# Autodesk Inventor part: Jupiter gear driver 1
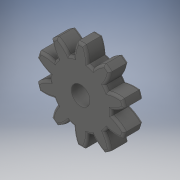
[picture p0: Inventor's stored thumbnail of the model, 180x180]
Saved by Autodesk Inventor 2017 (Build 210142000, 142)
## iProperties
Created: 2016-05
Part Number: Jupiter gear driver 1
Material: Generic
Document SubType Name: Modeling
Designer: Stan
Density: 1 g/cm^3
Appearance: Gray
Author: Stan
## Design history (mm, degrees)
sketch "Sketch1"
  geometry: A1 r 11.357 centre (-12.259, -5.358) between (-9.02, 5.527) and (-14.115, 5.847); A2 r 11.357 centre (-12.259, -5.358) between (-9.02, 5.527) and (-14.115, 5.847); A3 r 11.357 centre (1.307, 13.315) between (-9.922, 11.617) and (-8.044, 6.87); A4 r 11.357 centre (1.307, 13.315) between (-9.922, 11.617) and (-8.044, 6.87); A5 r 11.357 centre (-6.769, -11.54) between (-10.546, -0.83) and (-14.856, -3.567); A6 r 11.357 centre (-6.769, -11.54) between (-10.546, -0.83) and (-14.856, -3.567); A7 r 11.357 centre (-6.769, 11.54) between (-14.856, 3.567) and (-10.546, 0.83); A8 r 11.357 centre (-6.769, 11.54) between (-14.856, 3.567) and (-10.546, 0.83); A9 r 11.357 centre (1.307, -13.315) between (-8.044, -6.87) and (-9.922, -11.617); A10 r 11.357 centre (1.307, -13.315) between (-8.044, -6.87) and (-9.922, -11.617); A11 r 11.357 centre (-12.259, 5.358) between (-14.115, -5.847) and (-9.02, -5.527); A12 r 11.357 centre (-12.259, 5.358) between (-14.115, -5.847) and (-9.02, -5.527); A13 r 11.357 centre (8.884, -10.004) between (-2.47, -10.287) and (-1.199, -15.231); A14 r 11.357 centre (8.884, -10.004) between (-2.47, -10.287) and (-1.199, -15.231); A15 r 11.357 centre (-13.067, -2.871) between (-7.983, -13.027) and (-4.048, -9.774); A16 r 11.357 centre (-13.067, -2.871) between (-7.983, -13.027) and (-4.048, -9.774); A17 r 11.357 centre (13.067, -2.871) between (4.048, -9.774) and (7.983, -13.027); A18 r 11.357 centre (13.067, -2.871) between (4.048, -9.774) and (7.983, -13.027); A19 r 11.357 centre (-8.884, -10.004) between (1.199, -15.231) and (2.47, -10.287); A20 r 11.357 centre (-8.884, -10.004) between (1.199, -15.231) and (2.47, -10.287); A21 r 11.357 centre (12.259, 5.358) between (9.02, -5.527) and (14.115, -5.847); A22 r 11.357 centre (12.259, 5.358) between (9.02, -5.527) and (14.115, -5.847); A23 r 11.357 centre (-1.307, -13.315) between (9.922, -11.617) and (8.044, -6.87); A24 r 11.357 centre (-1.307, -13.315) between (9.922, -11.617) and (8.044, -6.87); A25 r 11.357 centre (6.769, 11.54) between (10.546, 0.83) and (14.856, 3.567); A26 r 11.357 centre (6.769, 11.54) between (10.546, 0.83) and (14.856, 3.567); A27 r 11.357 centre (6.769, -11.54) between (14.856, -3.567) and (10.546, -0.83); A28 r 11.357 centre (6.769, -11.54) between (14.856, -3.567) and (10.546, -0.83); A29 r 11.357 centre (-1.307, 13.315) between (8.044, 6.87) and (9.922, 11.617); A30 r 11.357 centre (-1.307, 13.315) between (8.044, 6.87) and (9.922, 11.617); A31 r 11.357 centre (12.259, -5.358) between (14.115, 5.847) and (9.02, 5.527); A32 r 11.357 centre (12.259, -5.358) between (14.115, 5.847) and (9.02, 5.527); A33 r 11.357 centre (-8.884, 10.004) between (2.47, 10.287) and (1.199, 15.231); A34 r 11.357 centre (-8.884, 10.004) between (2.47, 10.287) and (1.199, 15.231); A35 r 11.357 centre (13.067, 2.871) between (7.983, 13.027) and (4.048, 9.774); A36 r 11.357 centre (13.067, 2.871) between (7.983, 13.027) and (4.048, 9.774); A37 r 11.357 centre (1.307, 13.315) between (-9.922, 11.617) and (-8.044, 6.87); A38 r 11.357 centre (-12.259, -5.358) between (-9.02, 5.527) and (-14.115, 5.847); A39 r 11.357 centre (-6.769, 11.54) between (-14.856, 3.567) and (-10.546, 0.83); A40 r 11.357 centre (-6.769, -11.54) between (-10.546, -0.83) and (-14.856, -3.567); A41 r 11.357 centre (-12.259, 5.358) between (-14.115, -5.847) and (-9.02, -5.527); A42 r 11.357 centre (1.307, -13.315) between (-8.044, -6.87) and (-9.922, -11.617); A43 r 11.357 centre (-13.067, -2.871) between (-7.983, -13.027) and (-4.048, -9.774); A44 r 11.357 centre (8.884, -10.004) between (-2.47, -10.287) and (-1.199, -15.231); A45 r 11.357 centre (-8.884, -10.004) between (1.199, -15.231) and (2.47, -10.287); A46 r 11.357 centre (13.067, -2.871) between (4.048, -9.774) and (7.983, -13.027); A47 r 11.357 centre (-1.307, -13.315) between (9.922, -11.617) and (8.044, -6.87); A48 r 11.357 centre (12.259, 5.358) between (9.02, -5.527) and (14.115, -5.847); A49 r 11.357 centre (6.769, -11.54) between (14.856, -3.567) and (10.546, -0.83); A50 r 11.357 centre (6.769, 11.54) between (10.546, 0.83) and (14.856, 3.567); A51 r 11.357 centre (12.259, -5.358) between (14.115, 5.847) and (9.02, 5.527); A52 r 11.357 centre (-1.307, 13.315) between (8.044, 6.87) and (9.922, 11.617); A53 r 11.357 centre (13.067, 2.871) between (7.983, 13.027) and (4.048, 9.774); A54 r 11.357 centre (-8.884, 10.004) between (2.47, 10.287) and (1.199, 15.231); A55 r 11.357 centre (8.884, 10.004) between (-1.199, 15.231) and (-2.47, 10.287); A56 r 11.357 centre (-13.067, 2.871) between (-4.048, 9.774) and (-7.983, 13.027); A57 r 11.357 centre (-13.067, 2.871) between (-4.048, 9.774) and (-7.983, 13.027); A58 r 11.357 centre (-13.067, 2.871) between (-4.048, 9.774) and (-7.983, 13.027); A59 r 11.357 centre (8.884, 10.004) between (-1.199, 15.231) and (-2.47, 10.287); A60 r 11.357 centre (8.884, 10.004) between (-1.199, 15.231) and (-2.47, 10.287); A61 r 11.357 centre (1.307, 13.315) between (-9.922, 11.617) and (-8.044, 6.87); A62 r 11.357 centre (-13.067, 2.871) between (-4.048, 9.774) and (-7.983, 13.027); A63 r 11.357 centre (8.884, 10.004) between (-1.199, 15.231) and (-2.47, 10.287); A64 r 11.357 centre (-8.884, 10.004) between (2.47, 10.287) and (1.199, 15.231)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; 1 further point
  constraints: 160 point on circle, 80 centre point, 8 horizontal alignment, 8 vertical alignment, 224 other
  dimensions: "d0" = 0 dimension on point (0, 0); "d1" = 0 dimension on point (0, 0)
extrude "Extrusion1" new body sketch "Sketch1" distance "d2" = 6.35; taper "d3" = 0 deg
sketch "Sketch2"
  geometry: C1 r 3.175 at (0, 0); 1 further point
  constraints: 1 centre point, 1 coincident
  dimensions: "d4" = 6.35 diameter of C1
extrude "Extrusion2" cut sketch "Sketch2" distance "d5" = 6.35; taper "d6" = 0 deg
fillet "Fillet1" dims "d7" = 0.79375
fillet "Fillet2" dims "d8" = 0.79375
body "Solid1"
